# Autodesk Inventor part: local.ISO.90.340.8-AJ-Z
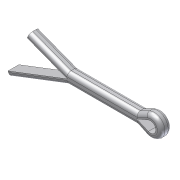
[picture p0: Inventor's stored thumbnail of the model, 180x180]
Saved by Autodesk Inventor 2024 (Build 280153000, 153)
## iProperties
Company: ATC
_DisabledCommands: 0
Created: 2023-03
Part Number: local.ISO.90.340.8-AJ-Z
Material: Standard
Description: Zawleczka - zmodyfikowana
Vendor: Autodesk Inc.
Document SubType Name: Modeling
Standard: ISO 1234
Designer: Andrzej Jaskulski
Size Designation: 1.6 x 14
Density: 1 g/cm^3
Appearance: Domyślna
Checked By: A.J.
Engr Approved By: Andrzej Jaskulski
Mfg Approved By: Andrzej Jaskulski
Authority: A.J.
Classification: un/spsc 31163204
Author: Andrzej Jaskulski
Revision Number: 1/24
Title: A.J.: Kurs R2024-MEP
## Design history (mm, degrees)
sketch "Szkic1"
  geometry: L1 (0, 0.7)-(9, 0.7); L2 (0, -0.7)-(9, -0.7); L3 (9, 0.7)-(14, 2.616); L4 (14, 2.616)-(14.234, 2.005); L5 (14.234, 2.005)-(9, 0); L6 (9, 0)-(16.734, -2.963); L7 (16.734, -2.963)-(16.5, -3.573); L8 (16.5, -3.573)-(9, -0.7); L9 (0, 0)-(-1.528, -0.645); L10 (0, 0)-(-1.528, 0.645); L11 (0, 0.7)-(0, -0.7); L12 (0, 0.7)-(-1.204, 1.267); L13 (0, -0.7)-(-1.204, -1.267); L14 (-3.2, 0)-(9, 0); L15 (9, 0.7)-(9, -0.7); A1 r 1.4 centre (-1.8, 0) between (-1.204, 1.267) and (-1.204, -1.267); A2 r 0.7 centre (-1.8, 0) between (-1.528, 0.645) and (-1.528, -0.645); 1 further point
  constraints: 30 end point, 5 point on circle, 4 parallel, 4 perpendicular, 4 point on line, 4 tangent, 2 centre point, 2 midpoint, 1 coincident, 1 horizontal
  dimensions: "d0" = 9 distance of L1.start L1.end (= MSIAB); "d1" = 14 horizontal distance of L1.start L3.end (= SNLG); "d2" = 159.037 deg angle of L1 L3; "d3" = 159.037 deg angle of L2 L8; "d4" = 2.5 horizontal distance of L3.end L7.end (= LGDIF); "d5" = 0.7 radius of A2 (= -0.5 x SNND1 + 0.5 x KBR); "d6" = 1.4 radius of A1 (= 0.5 x KBR); "d7" = 0.7 distance from line of L1 L9.start (= 0.5 x SNND1); "d8" = 0.7 distance between parallel lines of L2 L14 (= 0.5 x SNND1); "d9" = 1.8 distance from line of L11 A1.centre (= KOL - 0.5 x KBR)
extrude "Bryła" new body sketch "Szkic1" stored distance "d10" = 1.4 (= SNND1); taper "d11" = 0 deg
node "Oś"
node "Bryła1"
node "Korpusy bryłowe"
node "Korpusy powierzchniowe"
fillet "Zaokrąglenie" dims "d12" = 0.49 (= 0.35 x SNND1)
other parameters: "SNND" = 1.6 [user parameter], "SNLG" = 14 [user parameter; used in 1 equation term], "SNND1" = 1.4 [user parameter; used in 5 equation terms], "KBR" = 2.8 [user parameter; used in 3 equation terms], "KOL" = 3.2 [user parameter; used in 1 equation term], "LGDIF" = 2.5 [user parameter; used in 1 equation term], "MSIAB" = 9 [user parameter; used in 1 equation term], "NNDMIN" = 5.5 [user parameter], "NNDMAX" = 7 [user parameter], "DSH" = 3.3 [user parameter]
